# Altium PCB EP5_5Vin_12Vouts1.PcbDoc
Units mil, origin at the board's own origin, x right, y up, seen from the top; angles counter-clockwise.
Board outline 1250 x 850 mil, 2 copper layers (Top Layer, Bottom Layer), stack 62 mil thick; 30 components, 16 nets, 67 pads, 9 vias.
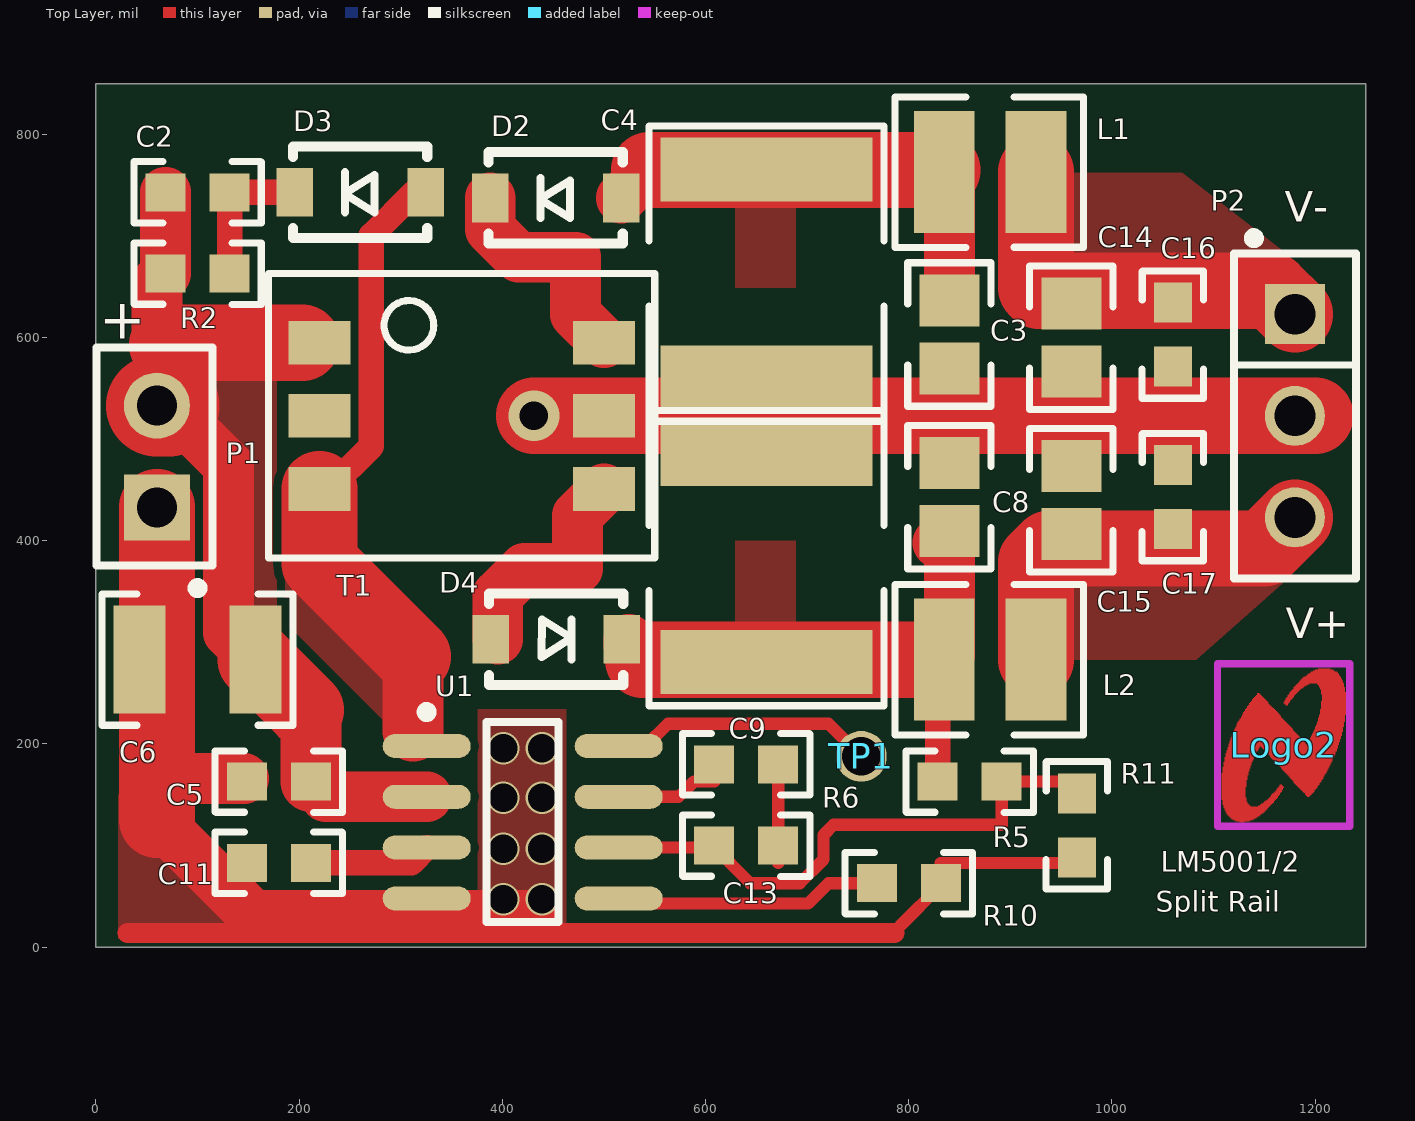
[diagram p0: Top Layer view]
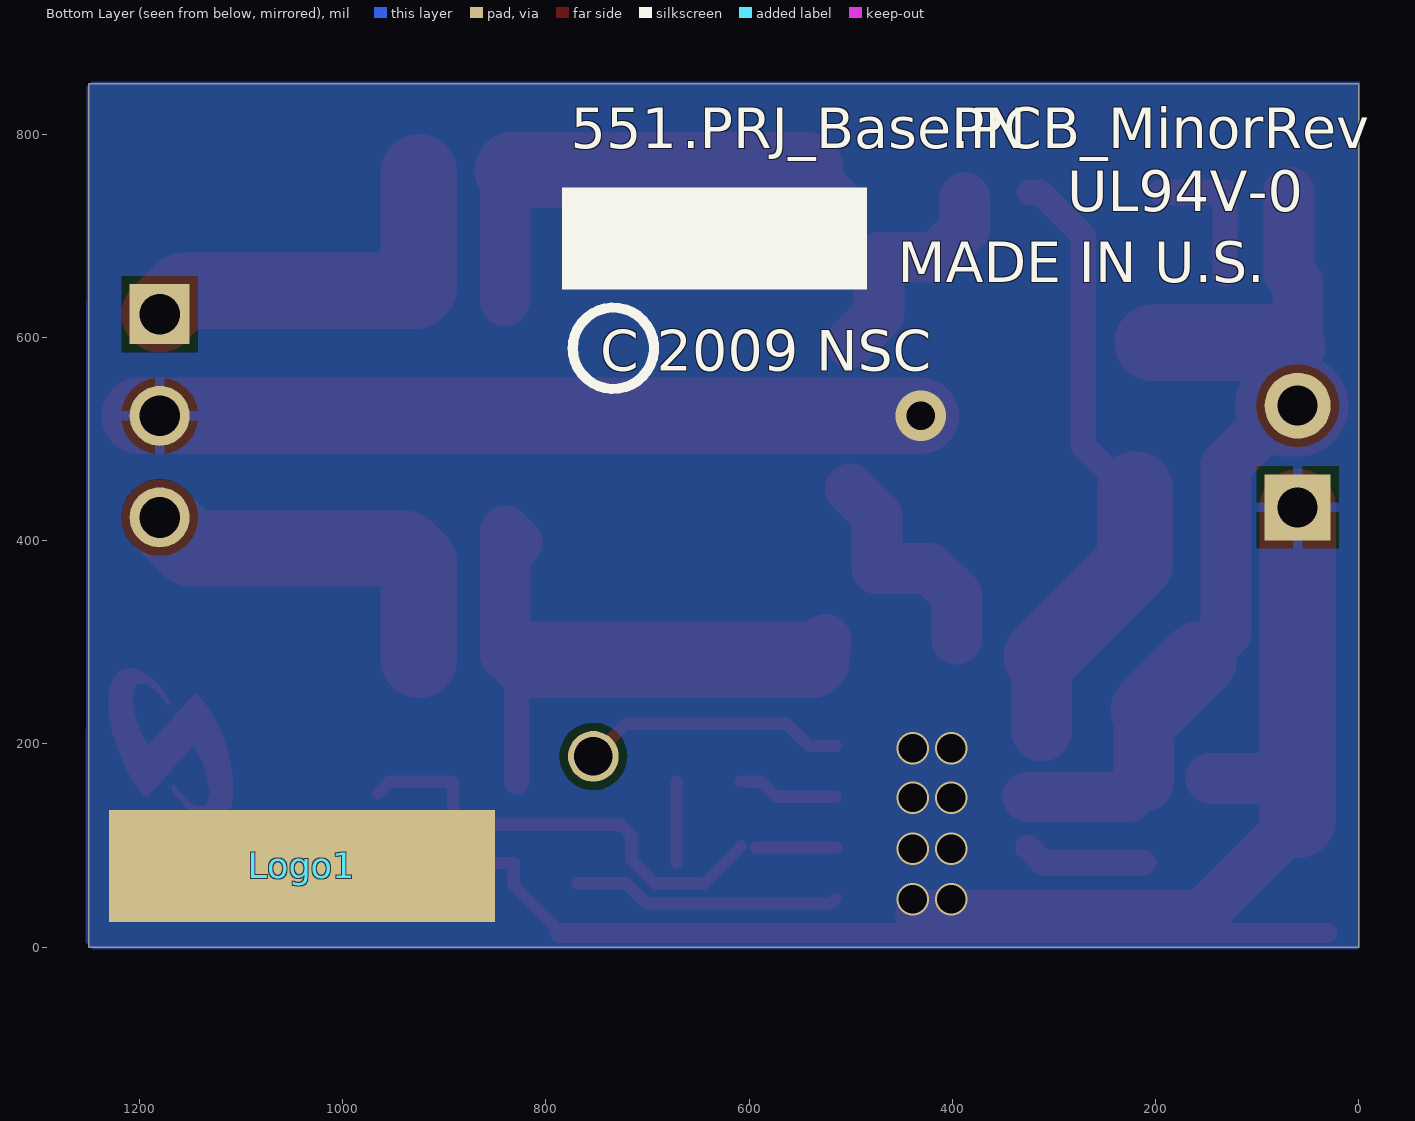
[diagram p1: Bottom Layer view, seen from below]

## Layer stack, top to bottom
Top Layer: signal copper 2
Dielectric: core 58, FR-4, Dk 4.8
Bottom Layer: signal copper 2

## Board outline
0,0 0,850 1250,850 1250,0

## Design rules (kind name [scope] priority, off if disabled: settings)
Clearance [All] p1: gap=8
ComponentClearance [All] p1: gap=40 collisioncheckmode=3 verticalgap=10 showdistances=FALSE
DiffPairsRouting [All] p1: maxlimit=100 minlimit=10 mostfreqgap=10 maxuncoupledlength=1000
FanoutControl Fanout_LCC [IsLCC] p1: bgadir=Out bgaviamode=Centered fanoutstyle=Auto fanoutdirection=Alternating viagrid=1 // Fanout_LCC (Default Rule)
FanoutControl Fanout_BGA [IsBGA] p2: bgadir=Out bgaviamode=Centered fanoutstyle=Auto fanoutdirection=Alternating viagrid=1 // Fanout_BGA (Default Rule)
FanoutControl Fanout_Default [All] p4: bgadir=Out bgaviamode=Centered fanoutstyle=Auto fanoutdirection=Alternating viagrid=1 // Fanout_Default (Default Rule)
FanoutControl Fanout_Small [(CompPinCount < 5)] p5: bgadir=Out bgaviamode=Centered fanoutstyle=Auto fanoutdirection=OutThenIn viagrid=1 // Fanout_Small (Default Rule)
HoleSize [All] p1: absolutevalues=TRUE maxlimit=251 minlimit=8 maxpercent=80.000 minpercent=20.000
MinimumAnnularRing [All] p1: minimumring=2
MinimumSolderMaskSliver MinimumSolderMaskSliver_1 [InComponent(Logo1)] p1: minsoldermaskwidth=1
MinimumSolderMaskSliver [All] p2: minsoldermaskwidth=4
PlaneConnect [All] p1: planeconnectstyle=Relief reliefexpansion=10 reliefentries=4 reliefconductorwidth=10 reliefairgap=10
PolygonConnect PolygonConnect_LOGO [IsPoly vs InComponent(Logo1)] p1: connectstyle=Direct reliefconductorwidth=10 reliefentries=4 polygonreliefangle="90 Angle"
PolygonConnect PolygonConnect_1 [All vs IsNamedPolygon('Bottom Layer-GND')] p2: connectstyle=Relief reliefconductorwidth=10 reliefentries=4 polygonreliefangle="90 Angle"
PolygonConnect [All] p3: connectstyle=Direct reliefconductorwidth=10 reliefentries=4 polygonreliefangle="90 Angle"
RoutingVias [All] p1: holewidth=16 width=32 viastyle="Through Hole" minholewidth=10 minwidth=25 maxholewidth=30 maxwidth=40
SilkToSilkClearance [All] p1: silktosilkclearance=5
SilkscreenOverComponentPads [All] p1: minsilkscreentomaskgap=5
SolderMaskExpansion [All] p1: expansion=3
TestPointUsage [All] p1: valid=2 allowmultiple=FALSE
Testpoint [All] p1: side=15 testpointundercomponent=TRUE minsize=40 maxsize=100 preferedsize=60 minholesize=0 maxholesize=40 preferedholesize=32 testpointgrid=1 style=1023 order=0123456789
Width [All] p1: maxlimit=100 minlimit=6 preferedwidth=20
13 further rules are at their usual default settings.

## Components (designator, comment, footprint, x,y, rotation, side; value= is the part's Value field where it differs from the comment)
C2 "C1608X7R1H103K" 0603 100,743 r0 top
C3 "C0805C104J5RACTU" 0805 840,603 r270 top
C4 "0805YD106MAT2A" 2220 660,663 r90 top
C5 "GRM188R71E104KA01D" 0603 180,163 r180 top
C6 "C1210C106K8PACTU" 1210 100,283 r180 top
C8 "C0805C104J5RACTU" 0805 840,443 r270 top
C9 "0805YD106MAT2A" 2220 660,383 r90 top
C11 "GRM188R71C105KA12D" 0603 180,83 r180 top
C13 "GRM188R71E104KA01D" 0603 640,100 r180 top
C14 "EMK212BJ106KG-T" 0805 960,600 r270 top
C15 "EMK212BJ106KG-T" 0805 960,440 r270 top
C16 "C1608X7R1H103K" 0603 1060,603 r270 top
C17 "C1608X7R1H103K" 0603 1060,443 r270 top
D2 "PMEG6010CEH,115" SOD-123 452.5,737.5 r180 top
D3 "BAT41ZFILM" SOD-123 260,743 r180 top
D4 "PMEG6010CEH,115" SOD-123 453,303 r0 top
L1 "ME3220-102MLB" ME3220 880,763 r0 top
L2 "ME3220-102MLB" ME3220 880,283 r0 top
Logo1 "PCB Logo" Logo_SolderMask_Small 1040,80 r180 bottom
Logo2 "PCB Logo" Worldmark_CopperSolderMask_Small 1169,199 r0 top
P1 "TSW-102-07-T-S" TSW-102-07-X-S 60,483 r90 top
P2 "TSW-103-07-T-S" TSW-103-07-X-S 1180,523 r270 top
R2 "CRCW060310k0JNEA" 0603 100,663 r0 top
R5 "CRCW060316k5FKEA" 0603 860,163 r0 top
R6 "CRCW0603249RFKEA" 0603 640,180 r0 top
R10 "CRCW060320k5FKEA" 0603 800,63 r180 top
R11 "CRCW06031K91FKEA" 0603 965.5,120 r270 top
T1 "RL-9400" S32890 360,523 r0 top
TP1 "TESTPOINT" TESTPOINT 753.24,187.83 r0 top
U1 "LM5001MA" M08A_N 420,123 r0 top

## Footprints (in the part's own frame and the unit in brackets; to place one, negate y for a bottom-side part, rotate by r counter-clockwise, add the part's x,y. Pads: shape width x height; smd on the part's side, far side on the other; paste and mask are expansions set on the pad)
0603 [mm] "0603 from SM-752 data"
  rect 1x0.95 smd: 1(-0.8,0) 2(0.8,0)
  silkscreen extent -1.59,-0.77 1.59,0.77, body extent -0.88,-0.48 0.87,0.48, height 0.85
0805 [mm] "0805 from SM-752 data"
  rect 1.3x1.5 smd: 1(-0.85,0) 2(0.85,0)
  silkscreen extent -1.79,-1.04 1.79,1.04, body extent -1.1,-0.72 1.1,0.72, height 1.1
1210 [mm] "1210 from SM-752 data"
  rect 1.3x2.7 smd: 1(-1.45,0) 2(1.45,0)
  silkscreen extent -2.39,-1.64 2.39,1.64, body extent -1.7,-1.35 1.7,1.35, height 1.35
2220 [mm] "Chip Capacitor, Body 5.7x5.0mm, IPC Medium Density"
  rect 1.6x5.3 smd: 1(-2.6,0) 2(2.6,0)
  silkscreen extent -3.69,-2.94 3.69,2.94, body extent -2.95,-2.63 2.95,2.63, height 1.35
Logo_SolderMask_Small [mil]
  rect 380x110 smd paste-55 mask-55: 0(0,0)
M08A_N [mm] "SOIC, 8-Leads, Body 4.9x3.9mm, Pitch 1.27mm, IPC Medium Density"
  oval 2.2x0.6 smd: 1(-2.4,1.905) 2(-2.4,0.635) 3(-2.4,-0.635) 4(-2.4,-1.905) 5(2.4,-1.905) 6(2.4,-0.635) 7(2.4,0.635) 8(2.4,1.905)
  silkscreen extent -2.52,-2.5 0.9,2.88, body extent -2,-2.5 2,2.5, height 1.75
ME3220 [mm] "Coilcraft SMT Power Inductor ME3220 inductors"
  rect 1.52x3.05 smd: 1(-1.145,0) 2(1.145,0)
  silkscreen extent -2.38,-1.88 2.34,1.88, body extent -1.75,-1.41 1.75,1.4
S32890 [mil] "Renco recommended land pattern"
  rect 61x43 smd: 1(-140,72) 2(-140,0) 3(-140,-72) 4(140,-72) 5(140,0) 6(140,72)
  silkscreen extent -190,-140 190,140, body extent -120,-137 120,138, height 225
SOD-123 [mm] "On Semi recommended land pattern"
  rect 0.915x1.22 smd: 1(-1.637,0) 2(1.637,0)
  silkscreen extent -1.68,-1.14 1.68,1.14, body extent -1.42,-0.9 1.42,0.9, height 1.35
TESTPOINT [mm]
  round 1.27 hole 0.965: 1(0,0)
TSW-102-07-X-S [mm] "Samtec 100 mil 1x2 head, 230 mil above insulator"
  rect 1.65x1.65 hole 1 mask+0: 1(-1.27,0)
  round 1.65 hole 1 mask+0: 2(1.27,0)
  silkscreen extent -3.42,-1.38 2.72,1.51, body extent -2.54,-1.27 2.54,1.27, height 8.38
TSW-103-07-X-S [mm] "Samtec Header, 100mil, 1x3"
  rect 1.5x1.5 hole 1.02: 1(-2.54,0)
  round 1.5 hole 1.02: 2(0,0) 3(2.54,0)
  silkscreen extent -4.57,-1.52 4.06,1.52, body extent -3.81,-1.27 3.81,1.27, height 8.38
Worldmark_CopperSolderMask_Small [mil]
  Top Layer region: 667 vertices and 0 holes, not listed, extent -61,-76 61,75
  Top Layer keep-out lines w7: -65,-80 -65,80 65,80 65,-80 -65,-80

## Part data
C2: library part GRM188R71H103KA01D, "Ceramic, X7R, 50V, 10%"
C3 C8: "Ceramic, X7R, 50V, 5%"
C4 C9: library part C5750X5R1C476M, "Ceramic, X5R, 16V, 20%"
C5 C13: "Ceramic, X7R, 25V, 10%"
C6: "Ceramic, X5R, 10V, 10%"
C11: "Ceramic, X7R, 16V, 10%"
C14 C15: "Ceramic, X5R, 16V, 10%"
C16 C17: "Ceramic, X7R, 50V, 10%"
D2 D4: library part 1N5819HW-7-F, "Vr = 40V, Io = 1A, Vf = 0.45V"
D3: "Vr = 100V, Io = 0.2A, Vf = 1V"
L1 L2: "Drum Core, 2.6A, 0.058 Ohm"
Logo1 Logo2: library part "NSC Logo", "National Semiconductor logo or worldmark"
P1: "Header, TH, 100mil, 1x2, Tin plated, 230 mil above insulator"
P2: "Header, TH, 100mil, 1x3, Tin plated, 230 mil above insulator"
R2: "5%, 0.1W"
R5 R6 R10: "1%, 0.1W"
R11: library part CRCW06031k50JNEA, "5%, 0.1W"
T1: library part RL-8800, "Transformer"
TP1: "TEST POINT.  No entry in BOM."
U1: "High Voltage Switch Mode Regulator"

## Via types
v1: diameter 32, hole 28, Top Layer to Bottom Layer, 8 vias
v2: diameter 50, hole 28, Top Layer to Bottom Layer, 1 vias

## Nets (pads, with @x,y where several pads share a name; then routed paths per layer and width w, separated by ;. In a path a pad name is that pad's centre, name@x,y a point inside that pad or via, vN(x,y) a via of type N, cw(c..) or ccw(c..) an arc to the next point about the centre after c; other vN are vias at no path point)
GND: C3.2 C4.1 C5.2 C6.2 C8.1 C9.2 C11.2 C14.2 C15.1 C16.2 C17.1 Logo1.0 P1.1 P2.2 R10.1 R11.2 T1.5 U1.4 | length 2536
  Top Layer w12: 791.36,20.8 831.5,60.94 831.5,83 R11.2@965.5,83
  Top Layer w20: 31,14 786,14
  Top Layer w50: 60,125.5 151.5,34 ; 60,166 C5.2@145.5,166 ; 154.2,31.3 430.92,31.3
  Top Layer w75: 60,125.5 60,166 P1.1 ; v2(431,523) P2.2@1200,523
  other v1: 401,47 439,47 401,97 439,97 401,147 439,147 401,196 439,196
NetC2_1: C2.1 C5.1 C6.1 P1.2 R2.1 T1.1 U1.2 | length 828.9
  Top Layer w50: C2.1 R2.1 60,654.5 60,593 70,593 ; P1.2@71.63,533 130.5,474.13 130.5,309.59 C6.1 ; C5.1@226.5,148 U1.2
  Top Layer w60: C5.1 211.5,228.59
  Top Layer w75: 70,593 72,595 T1.1@203,595 ; C6.1 206.54,233.54
  Top Layer w100: P1.2 P1.2@71.63,533
NetC2_2: C2.2 D3.2 R2.2 | length 144
  Top Layer w25: R2.2 C2.2 D3.2
NetC3_1: C3.1 C4.2 D2.1 L1.1 | length 458.8
  Top Layer w50: D2.1 544.47,765 ; L1.1@832.92,765 840,757.92 C3.1
  Top Layer w75: 544.47,765 L1.1@832.92,765
NetC8_2: C8.2 C9.1 D4.2 L2.1 R5.1 | length 555.5
  Top Layer w25: R5.1 L2.1@828.5,276.58
  Top Layer w50: D4.2@524.47,303 524.47,296.89 538.36,283 ; C8.2@828.5,398.04 C8.2 L2.1@840,288.08
  Top Layer w75: 538.36,283 L2.1@816.84,283
NetC11_1: C11.1 U1.3 | length 120.2
  Top Layer w25: C11.1 310.51,83 U1.3
NetC13_1: C13.1 R6.2 | length 80
  Top Layer w12: C13.1@671.5,83 R6.2@671.5,163
NetC13_2: C13.2 R5.2 R11.1 U1.6 | length 537
  Top Layer w12: U1.6 C13.2@593.5,98 ; C13.2@607.75,99.25 644,63 692.68,63 716,86.32 716,110.5 726,120.5 891.5,120.5 R5.2 954,163 R11.1
NetC14_1: C14.1 C16.1 L1.2 P2.1 | length 379.7
  Top Layer w75: L1.2 925.08,649 928.08,646 1060,646 1157,646 P2.1
NetC15_2: C15.2 C17.2 L2.2 P2.3 | length 398.3
  Top Layer w75: L2.2 925.08,379 938.57,392.49 1060,392.49 1149.49,392.49 P2.3 P2.3@1159.37,402.37
NetD2_2: D2.2 T1.6 | length 221.7
  Top Layer w50: D2.2 388.03,706.97 416.02,678.98 472.01,678.98 472.01,622.99 T1.6
NetD3_1: D3.1 T1.3 U1.1 | length 623.1
  Top Layer w25: T1.3 228.99,451 271,493.01 271,700.53 313.47,743 D3.1
  Top Layer w60: 312,213 312,286
  Top Layer w75: T1.3 220,378 312,286
NetD4_1: D4.1 T1.4 | length 221.9
  Top Layer w50: D4.1@395.53,303 395.53,346.53 421.65,372.65 473.88,372.65 473.88,424.88 T1.4
NetR6_1: R6.1 U1.7 | length 100.2
  Top Layer w12: U1.7 573.5,148 588.5,163 R6.1@608.5,163
NetR10_2: R10.2 U1.5 | length 264.4
  Top Layer w12: U1.5 519.49,43 700.97,43 720.97,63 R10.2
NetTP1_1: TP1.1 U1.8 | length 261.2
  Top Layer w12: U1.8 541,198 563,220 721.07,220 TP1.1
pads on no net: T1.2

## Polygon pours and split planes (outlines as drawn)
NetD3_1 on Top Layer "Top Layer-No Net 2" (solid, pour order 1005): 184,370 184,322 287,219 285,221 285,267 285,269 184,370
NetC2_1 on Top Layer "Top Layer-No Net 1" (solid, pour order 1003): 176,306 178,308 178,570 108,570 107,571 111,567 111,310 172,310 176,306
GND on Top Layer "Top Layer-No Net" (solid, pour order 1002): 376,234 463,234 463,8 376,8
NetC15_2 on Top Layer "Top Layer-No Net 4" (solid, pour order 1001): 951,283 1082.82,283 1168,358.06 1157.86,367 951,367 951,283
NetC14_1 on Top Layer "Top Layer-No Net 3" (solid, pour order 1004): 1175,680 1069,762 958,762 958,682.32 956,680.77 957,680 1175,680
NetC3_1 on Top Layer "Top Layer-0805" (solid, pour order 1000): 629,729 689,729 689,649 629,649
NetC8_2 on Top Layer "Top Layer-0805P" (solid, pour order 1001): 629,400 689,400 689,320 629,320
GND on Top Layer "Top Layer-GND_Top" (solid, pour order 1000): 22,121 22,8 155,8 155,17 22,150 22,121
GND on Bottom Layer "Bottom Layer-GND1" (solid, pour order 1000): 365,258 506,258 478,230 478,11 341,11
GND on Bottom Layer "Bottom Layer-GND" (solid, pour order 1000): 1252,847 1247,852 -1,852 -1,0 -2,-1 -1,-2 1253,-2
no net on Top Solder "Top Layer-0805" (solid): 629,738 689,738 689,649 629,649
no net on Top Solder "Top Layer-0805P" (solid): 629,400 689,400 689,301 629,301

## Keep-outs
Keep-Out Layer:
  text ".Layer_Name" at 577,-858.49 h20
  text "880" at 3117.5,-858.49 h20

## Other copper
Top Layer:
  text ".Layer_Name" at 577,-858.49 h20
  text "880" at 3117.5,-858.49 h20
Bottom Layer:
  text ".Layer_Name" at 577,-858.49 h20
  text "880" at 3117.5,-858.49 h20

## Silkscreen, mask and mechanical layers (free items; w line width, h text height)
Top Overlay:
  text "V-" at 1170,714 h30
  text "+" at 3,599 h40
  text "V+" at 1171,304 h30
  text "LM5001/2" at 1048,74 h20
  text "Split Rail" at 1043,35 h20
  text ".Layer_Name" at 577,-858.49 h20
  text "880" at 3117.5,-858.49 h20
Bottom Overlay:
  circle w10: c733.5,589.5 r40
  rectangle: 484,647.5 784,747.5
  text ".PCB_MinorRev" at 400.18,786.5 h40
  text ".PRJ_BasePN" at 665.5,786.5 h40
  text "551" at 775.5,786.5 h40
  text "UL94V-0" at 286.89,724.5 h40
  text "MADE IN U.S." at 453.5,654.5 h40
  text "C 2009 NSC" at 746.5,567.5 h40
  text ".Layer_Name" at 577,-858.49 h20
  text "880" at 3117.5,-858.49 h20
Top Paste:
  text ".Layer_Name" at 577,-858.49 h20
  text "881" at 3117.5,-858.49 h20
Bottom Paste:
  text ".Layer_Name" at 577,-858.49 h20
  text "881" at 3117.5,-858.49 h20
Top Solder:
  text ".Layer_Name" at 577,-858.49 h20
  text ".Layer_Name" at 577,-858.49 h20
  text "880" at 3117.5,-858.49 h20
Bottom Solder:
  text ".Layer_Name" at 577,-858.49 h20
  text "880" at 3117.5,-858.49 h20
Drill Guide:
  text ".Layer_Name" at 577,-858.49 h20
  text "880" at 3117.5,-858.49 h20
M1 Board Outline:
  the board outline again, w10
M2 Board Dimensions:
  rectangle: -0.5,-285.5 124.5,-160.5
  rectangle: 124.5,-410.5 499.5,-285.5
  lines w7: -0.5,-285.5 999.5,-285.5 ; 124.5,-410.5 124.5,-160.5 ; 249.5,-410.5 249.5,-160.5 ; 499.5,-410.5 499.5,-160.5 ; 749.5,-410.5 749.5,-160.5 ; -0.5,-410.5 999.5,-410.5 999.5,-160.5 -0.5,-160.5 -0.5,-410.5
  lines w10: -0.5,-475.5 -0.5,-455.5 ; 59.5,-485.5 -0.5,-465.5 ; 59.5,-445.5 -0.5,-465.5 ; 223.58,-465.5 -0.5,-465.5 ; 775.42,-465.5 999.5,-465.5 ; 939.5,-485.5 999.5,-465.5 ; 939.5,-445.5 999.5,-465.5 ; 999.5,-475.5 999.5,-455.5
  text "1000 (mil)" at 233.58,-501.49 h60
  text ".Layer_Name" at 577,-858.49 h20
  text "880" at 3117.5,-858.49 h20
M3 3D STEP Top:
  text ".Layer_Name" at 577,-858.49 h20
  text "880" at 3117.5,-858.49 h20
M4 3D STEP Bottom:
  text ".Layer_Name" at 577,-858.49 h20
  text "880" at 3117.5,-858.49 h20
M5 Assembly Top:
  text "COMPONENTS MARKED 'DNP' SHOULD NOT BE POPULATED, AND MAY NOT BE IN BILL OF MATERIALS" at 1153.5,-318.5 h20
  text ".Layer_Name" at 577,-858.49 h20
  text "880" at 3117.5,-858.49 h20
M6 Assembly Bottom:
  text "COMPONENTS MARKED 'DNP' SHOULD NOT BE POPULATED, AND MAY NOT BE IN BILL OF MATERIALS" at 1153.5,-318.5 h20
  text ".Layer_Name" at 577,-858.49 h20
  text "880" at 3117.5,-858.49 h20
M9 Title Sheet:
  drawing of 63 lines, arcs and shapes, not listed
  text "1" at 739.84,8036.5 h20
  text "2" at 3235.5,8036.5 h20
  text "3" at 5724.84,8036.5 h20
  text "4" at 8231.51,8036.5 h20
  text "5" at 10730.5,8036.5 h20
  text "6" at 13235.5,8036.5 h20
  text "A" at -416.5,6893.5 h20
  text "B" at -416.5,4513.5 h20
  text "B" at 14383.5,4513.5 h20
  text "C" at -416.5,2138.5 h20
  text "C" at 14383.5,2138.5 h20
  text "A" at 14433.5,1126.5 h20
  text "PROJECT TITLE:" at 11343.5,277.5 h20
  text ".PRJ_Title" at 11393.5,144.17 h20
  text "FILE NAME:" at 11343.5,-23.5 h20
  text ".PCB_File_Name_No_Path" at 11393.5,-143.5 h20
  text "D" at -416.5,-231.5 h20
  text "D" at 14383.5,-231.5 h20
  text "FAB DRAWING NUMBER:" at 11343.5,-313.5 h20
  text "551" at 11393.5,-468.49 h20
  text ".PRJ_BasePN" at 11588.5,-468.49 h20
  text ".PCB_MinorRev" at 11998.5,-468.49 h20
  text "National Semiconductor and/or its licensors do not warrant the accuracy or completeness of this specification" at 6374,-605.34 h20
  text "DESIGNED FOR:" at 11343.5,-623.5 h20
  text "or any information contained therein. National and/or its licensors do not warrant that this design will meet" at 6329.01,-718 h20
  text ".PRJ_Customer" at 11393.5,-763.5 h20
  text "the specifications, will be suitable for your application or fit for any particular purpose, or will operate in" at 6329.01,-830.67 h20
  text ".Layer_Name" at 577,-858.49 h20
  text "880" at 3117.5,-858.49 h20
  text "ALTIUM DESIGNER VERSION:" at 12888.5,-923.5 h20
  text "an implementation. National and/or its licensors do not warrant that the design is production worthy. You should" at 6329.01,-943.33 h20
  text ".print_Scale" at 11393.5,-1025.5 h20
  text "completely validate and test your design implementation to confirm the system functionality for your application." at 6374,-1056 h20
  text ".Application_BuildNumber" at 12938.5,-1056.83 h20
  text "1" at 739.84,-1263.5 h20
  text "2" at 3235.5,-1263.5 h20
  text "3" at 5724.84,-1263.5 h20
  text "4" at 8231.51,-1263.5 h20
  text "5" at 10730.5,-1263.5 h20
  text "6" at 13235.5,-1263.5 h20
M10 Fab Notes:
  text "Customizable Fab notes are in \"Fab Drawing Notes.doc\" located" at 10360,6195 h20
  text "in C:\Program Files\Altium Designer Winter 09\Templates\National" at 10335,6055 h20
  text ".Layer_Name" at 577,-858.49 h20
  text "880" at 3117.5,-858.49 h20
M11 Gerber Information:
  lines w7: -292,-930.17 6308,-930.17 ; -292,-726.83 6310,-726.83 ; -292,-523.5 -292,-1133.5 3713,-1133.5 6310,-1133.5 6310,-523.5 -291.5,-523.5 -291.5,-1133.5 1284,-1133.5 ; 2173,-1133.5 2173,-523.5 ; 4902,-1133.5 4902,-930.17
  text "ALL ARTWORK VIEWED FROM TOP SIDE" at -228.5,-655.67 h20
  text "PROJECT NAME =" at 2248,-655.67 h20
  text ".PRJ_Title" at 3117.5,-655.67 h20
  text "LAYER NAME =" at -228.5,-858.49 h20
  text "ARTWORK #    =" at 2248,-858.49 h20
  text ".prj_BasePN" at 3293.5,-858.49 h20
  text ".pcb_minorRev" at 3656.5,-858.49 h20
  text "NATIONAL SEMICONDUCTOR" at 4973,-1052.34 h20
  text "PLOT NAME =" at -228.5,-1064.34 h20
  text ".plot_File_Name" at 577,-1064.34 h20
  text "GENERATED    :" at 2248,-1064.34 h20
  text ".Print_Date" at 3117.5,-1064.34 h20
  text ".Print_Time" at 3846.5,-1064.34 h20
M12 Stackup:
  lines w7: 10260.5,7201.33 14180.5,7201.33 ; 10260.5,7335.43 14180.5,7335.43 ; 10200.5,6417.5 ccw(c10243.5,6417.5) 10243.5,6374.5 14197.5,6374.5 ccw(c14197.5,6417.5) 14240.5,6417.5 14240.5,7566.5 ccw(c14197.5,7566.5) 14197.5,7609.5 10243.5,7609.5 ccw(c10243.5,7566.5) 10200.5,7566.5 10200.5,6417.5
  text "The Stackup Legend below this is static." at 10605.5,7854.5 h20
  text "If you change the stackup, you need to change the Legend." at 10615.5,7724.5 h20
  text "Layer Stack Up Detail for: Ref_Design.PcbDoc" at 10260.5,7406.37 h20
  text "Layer" at 10260.5,7285.43 h20
  text "Gerber" at 11106.21,7285.43 h20
  text "Copper" at 11547.57,7285.43 h20
  text "Dielectric" at 12039.55,7285.43 h20
  text "Dielectric" at 12553.22,7285.43 h20
  text "Dielectric" at 13177.38,7285.43 h20
  text "Dielectric" at 13691.05,7285.43 h20
  text "Name" at 10260.5,7223.43 h20
  text "Document" at 11106.21,7223.43 h20
  text "Thickness" at 11547.57,7223.43 h20
  text "Height" at 12039.55,7223.43 h20
  text "Material" at 12553.22,7223.43 h20
  text "Constant" at 13177.38,7223.43 h20
  text "Type" at 13691.05,7223.43 h20
  text "Top Solder Mask" at 10260.5,7119.92 h20
  text "(.GTS)" at 11106.21,7119.92 h20
  text "0.4mil" at 12039.55,7119.92 h20
  text "Solder Resist" at 12553.22,7119.92 h20
  text "3.50" at 13177.38,7119.92 h20
  text "Top Layer" at 10260.5,6964.08 h20
  text "(.GTL)" at 11106.21,6964.08 h20
  text "2mil" at 11547.57,6964.08 h20
  text "58mil" at 12039.55,6886.17 h20
  text "FR-4" at 12553.22,6886.17 h20
  text "4.80" at 13177.38,6886.17 h20
  text "Core" at 13691.05,6886.17 h20
  text "Bottom Layer" at 10260.5,6808.25 h20
  text "(.GBL)" at 11106.21,6808.25 h20
  text "2mil" at 11547.57,6808.25 h20
  text "Bottom Solder Mask" at 10260.5,6652.42 h20
  text "(.GBS)" at 11106.21,6652.42 h20
  text "0.4mil" at 12039.55,6652.42 h20
  text "Solder Resist" at 12553.22,6652.42 h20
  text "3.50" at 13177.38,6652.42 h20
  text ".Layer_Name" at 577,-858.49 h20
  text "880" at 3117.5,-858.49 h20
M13 Component Bodies Top:
  text ".Layer_Name" at 577,-858.49 h20
  text "880" at 3117.5,-858.49 h20
M14 Component Bodies Bottom:
  text ".Layer_Name" at 577,-858.49 h20
  text "880" at 3117.5,-858.49 h20
M15 Courtyards Top:
  text ".Layer_Name" at 577,-858.49 h20
  text "880" at 3117.5,-858.49 h20
M16 Courtyards Bottom:
  text ".Layer_Name" at 577,-858.49 h20
  text "880" at 3117.5,-858.49 h20
Drill Drawing:
  text ".legend" at 10396.5,2516.5 h20
  text "Drill Table" at 10421.5,2331.5 h20
  text ".Layer_Name" at 577,-858.49 h20
  text "880" at 3117.5,-858.49 h20

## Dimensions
0,0 to 0,850 on M2 Board Dimensions
0,0 to 1250,0 on M2 Board Dimensions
